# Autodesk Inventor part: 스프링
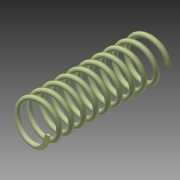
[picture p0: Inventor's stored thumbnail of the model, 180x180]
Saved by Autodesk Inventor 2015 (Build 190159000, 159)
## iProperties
Created: 2023-11
Part Number: 스프링
Material: 강철, 연강
Document SubType Name: Modeling
Designer: mdu-01
Density: 1 g/cm^3
Appearance: 기본값(1)
Author: mdu-01
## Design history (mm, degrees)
sketch "스케치1" dims "d0" = 0.6
  geometry: L1 (0, 0)-(2.35, 0); L2 (2.35, 0)-(2.35, 16); L3 (2.35, 16)-(0, 16); L4 (0, 16)-(0, 0); L5 (-2.75, 16)-(2.75, 16) reference; L6 (2.65, 0)-(2.65, 6.462); 1 further point
  constraints: 10 end point, 2 parallel, 2 perpendicular, 1 coincident, 1 collinear, 1 horizontal, 1 horizontal alignment, 1 vertical, 2 other
  dimensions: "d2" = 16 distance between parallel lines of L1 L3 (derived); "d16" = 0.1 distance from line of L5.end L6
feature "코일1" sketch "스케치1" pitch "d3" = 10; turns "d5" = 10; dims "d4" = 16 (= d2), "d6" = 0, angle "d7" = 90 deg, angle "d8" = 90 deg, "d9" = 0, "d10" = 0
sketch "스케치2"
  geometry: L1 (-2.65, 0)-(-2.05, 0) reference; 1 further point
  constraints: 1 horizontal alignment
extrude "돌출1" cut sketch "스케치2" stored distance "d11" = 0; taper "d12" = 0 deg
node "작업 평면1"
sketch "스케치3"
  geometry: L1 (0.3, 0)-(-0.3, 0) reference; 1 further point
  constraints: 1 horizontal alignment
extrude "돌출2" cut sketch "스케치3" stored distance "d14" = 0; taper "d15" = 0 deg
node "솔리드1"
node "참조1"
node "절단 모서리 투영1"
node "절단 모서리 투영2"
other parameters: "d13" = 0
